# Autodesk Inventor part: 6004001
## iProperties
Category: PARTsolutions
Created: 2007-09
Part Number: 6004001
Catalog Web Link: www.cadenas.de
Description: 6004001,6004001-M - Body
Document SubType Name: Modeling
Designer: PARTsolutions
Material: 1.0037 St 37-2
NB: 6004001
NN: 6004001,6004001-M
NT: Body
NBSYN: $MN.
LINA: 6004001
S: 6004
MN: 6004001
A: 0.8750
L: 2.8100
L1: 0.7500
L2: 2.5000
L3: 1.3200
L4: 0.0900
R1: 4.0000
R2: 2.7500
D1: 0.6650
D2: 0.1890
D3: 0.5020
H1: 1.4900
H2: 1.2100
KDM: 0.6755
NDM: 0.7500
W1: 0.6250
W2: 0.2500
CPP: 50.8000
NDM2: 0.000
KDM2: 0.000
L5: 0.000
L6: 0.000
D4: 0.000
KT: DUMMY
PSOL_IDENT_0: {\\partserver001.servicenet\dplatte\cadenas\23d-libs\destaco\industries\manual_clamps\straight_line_
PSOL_IDENT_1: action_clamps\through_hole_mount\6004_parts\6004_body.prj},158 {VTYP=3D},{NB=6004001},{LINA=6004001}
PSOL_IDENT_2: ,{NN=6004001,6004001-M},{DATE=19.06.2006 12:11:48},{GEOMDATE=19.06.2006},{VERSION=},{LINEID=10},{LIN
PSOL_IDENT_3: ESUBID=-1},{WBVAR=}  {NB=6004001},{LINA=6004001},{KT=DUMMY},{S=6004},{MN=6004001},{A=0.8750},{L=2.81
PSOL_IDENT_4: 00},{L1=0.7500},{L2=2.5000},{L3=1.3200},{L4=0.0900},{R1=4.0000},{R2=2.7500},{D1=0.6650},{D2=0.1890},
PSOL_IDENT_5: {D3=0.5020},{H1=1.4900},{H2=1.2100},{KDM=0.6755},{NDM=0.7500},{W1=0.6250},{W2=0.2500},{CPP=50.8000},
PSOL_IDENT_6: {NDM2=0.000},{KDM2=0.000},{L5=0.000},{L6=0.000},{D4=0.000}
Title: 6004001
Author: Cadenas PARTsolutions
Comments: Body
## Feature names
1. Revolution1
2. Extrusion1
3. Revolution2
4. Revolution3
5. Revolution4
6. Extrusion2
7. Revolution5
